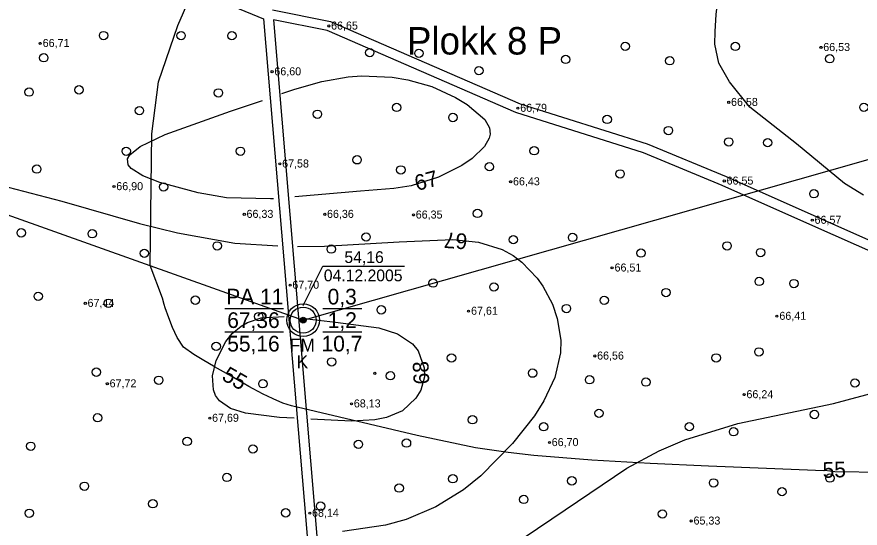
# Model space of a CAD drawing. Extents: x 532503 to 539665, y 6557663 to 6561526.
# Drawn here: x 534382.9 to 534640.9, y 6559631.8 to 6559788.4 of the extents above; entities that cross this region are included whole.
import ezdxf

# ---------------------------------------------------------------- set-up
doc = ezdxf.new("R2010")
doc.units = 0
for name, color, linetype in [('GEOLPUNKT', 7, 'Continuous'), ('HALJASTUS', 7, 'Continuous'), ('HORISONTAAL-EH2000', 7, 'Continuous'), ('KORGUS-EH2000', 7, 'Continuous'), ('Lamami horisontaal_EH2000', 7, 'Continuous'), ('Lõige', 7, 'Continuous'), ('Plokid', 7, 'Continuous'), ('Proovid', 7, 'Continuous'), ('TEE', 7, 'Continuous'), ('Veetase', 7, 'Continuous')]:
    doc.layers.add(name, color=color, linetype=linetype)

# ---------------------------------------------------------------- blocks, each defined once
blk = doc.blocks.new('METS')
at = {"layer": 'HALJASTUS'}
blk.add_circle((0, 0), 0.8, dxfattribs=at)

msp = doc.modelspace()

# ---------------------------------------------------------------- linework, layer by layer
at = {"layer": 'GEOLPUNKT'}
for p, q in [((534446.46, 6559699.1), (534464.46, 6559699.1)), ((534476.46, 6559699.1), (534488.46, 6559699.1)), ((534446.46, 6559691.9), (534464.46, 6559691.9)), ((534476.46, 6559691.9), (534488.46, 6559691.9))]:
    msp.add_line(p, q, dxfattribs=at)
for radius in [5, 4, 0.9, 0.801, 0.7, 0.6, 0.5, 0.4, 0.3, 0.2, 0.1]:
    msp.add_circle((534470.46, 6559695.5), radius, dxfattribs=at)
at = {"layer": 'HORISONTAAL-EH2000'}
for points in [[(534463.98, 6559764.86), (534467.88, 6559766.2), (534476.15, 6559768.55), (534484.2, 6559769.98), (534488.32, 6559770.29), (534497.69, 6559769.93), (534502.54, 6559769.12), (534509.88, 6559767.01), (534517.13, 6559763.69), (534520.66, 6559761.54), (534526.09, 6559756.93), (534527.51, 6559754.38), (534527.66, 6559752.47), (534527.37, 6559751.19), (534525.95, 6559748.65), (534522.22, 6559745.02), (534519, 6559742.82), (534511.9, 6559739.24), (534503.48, 6559736.65), (534498.24, 6559735.82), (534487.98, 6559735.02), (534467.95, 6559733.26)], [(534416.88, 6559743.1), (534416.74, 6559744.91), (534417.46, 6559746.14), (534420.54, 6559748.62), (534428.26, 6559752.34), (534448.28, 6559759.44), (534458, 6559762.8)], [(534461.38, 6559732.68), (534460.49, 6559732.6), (534447, 6559732.94), (534438.35, 6559734.48), (534426.58, 6559737.68), (534421.41, 6559739.72), (534417.82, 6559741.94), (534416.88, 6559743.1)], [(534304.83, 6559710.87), (534306.86, 6559714.66), (534312.1, 6559721.64), (534318.6, 6559727.68), (534323.47, 6559731.11), (534330.43, 6559734.83), (534334.03, 6559736.29), (534340.72, 6559738.23), (534345.25, 6559739.05), (534354.44, 6559739.68), (534368.46, 6559738.57), (534377.87, 6559736.8), (534396.57, 6559731.9), (534420.34, 6559725.11), (534432.05, 6559722.19), (534449.59, 6559719.1), (534462.68, 6559718.26)], [(534468.76, 6559718.08), (534476.98, 6559718.15), (534499.85, 6559719.5), (534516.26, 6559720.19), (534524.11, 6559719.37), (534531.39, 6559717.1), (534534.73, 6559715.26), (534537.38, 6559713.3), (534542.07, 6559708.39), (534543.84, 6559705.87), (534546.73, 6559700.39), (534548.23, 6559696.03), (534549.28, 6559689.36), (534549.16, 6559685.49), (534547.43, 6559677.98), (534544.1, 6559670.82), (534541.23, 6559666.25), (534534.5, 6559657.68), (534524.79, 6559647.82), (534519.55, 6559643.58), (534511.05, 6559638.29), (534501.98, 6559634.51), (534495.61, 6559632.72), (534482.49, 6559630.74)], [(534448.77, 6559691.44), (534451.45, 6559693.69), (534453.39, 6559694.79), (534457.61, 6559696.17), (534464.65, 6559696.66), (534464.69, 6559696.66)], [(534469.96, 6559696.06), (534480.31, 6559694.89), (534493.61, 6559693.12), (534499.34, 6559691.35), (534503.92, 6559688.26), (534505.65, 6559686.06), (534507.51, 6559680.93), (534507.61, 6559678.15), (534506.47, 6559674.09), (534504.99, 6559671.64), (534500.82, 6559667.76), (534495.95, 6559665.65), (534492.44, 6559664.96), (534485.3, 6559664.59), (534472.81, 6559665.21)], [(534467.75, 6559665.46), (534463.21, 6559665.69), (534452.84, 6559667), (534448.28, 6559668.45), (534444.83, 6559670.8), (534443.68, 6559672.4), (534442.99, 6559674.21), (534442.77, 6559678.48), (534443.83, 6559683.14), (534446.8, 6559689.01), (534448.77, 6559691.44)], [(534477.14, 6559615.14), (534484.93, 6559615.02), (534497.02, 6559615.08), (534503.03, 6559615.59), (534509.26, 6559616.62), (534521.34, 6559620.21), (534531.56, 6559625.05), (534538.08, 6559628.91), (534550.68, 6559637.44), (534569.5, 6559650.15), (534579.4, 6559655.53), (534587.21, 6559658.85), (534603.5, 6559663.82), (534632.76, 6559670.02), (534646.85, 6559673.77), (534665.59, 6559678.92), (534675.04, 6559680.97), (534698.41, 6559684.27), (534708.64, 6559686.35)]]:
    msp.add_lwpolyline(points, dxfattribs=at)
at = {"layer": 'KORGUS-EH2000'}
for centre in [(534478.31, 6559785.57), (534390, 6559780.24), (534628.91, 6559779.01), (534460.95, 6559771.57), (534536.18, 6559760.39), (534600.69, 6559762.19), (534463.34, 6559743.34), (534533.97, 6559737.88), (534599.34, 6559738.11), (534412.59, 6559736.41), (534452.45, 6559727.91), (534477.07, 6559727.91), (534504.21, 6559727.71), (534626.26, 6559726.1), (534564.99, 6559711.49), (534466.47, 6559706.22), (534403.8, 6559700.65), (534521.08, 6559698.25), (534615.42, 6559696.7), (534559.72, 6559684.53), (534492.42, 6559679.21), (534410.54, 6559676.03), (534605.42, 6559672.7), (534485.27, 6559669.88), (534441.9, 6559665.48), (534545.83, 6559658.03), (534472.48, 6559636.39), (534589.22, 6559634.01)]:
    msp.add_circle(centre, 0.32, dxfattribs=at)
at = {"layer": 'Lamami horisontaal_EH2000'}
for points in [[(534641.96, 6559733.8), (534636.15, 6559737.35), (534621.41, 6559749.49), (534607.16, 6559760.68), (534600.88, 6559768.5), (534597.64, 6559774.18), (534596.39, 6559780.02), (534596.55, 6559783.91), (534596.82, 6559789.06), (534597.63, 6559796.25), (534601.08, 6559812.52), (534601.39, 6559813.21), (534608.53, 6559834.71), (534618.81, 6559854.93), (534624.39, 6559863.19), (534625.8, 6559864.95), (534629.67, 6559870.31), (534637.21, 6559879.48), (534638.05, 6559880.42), (534643.05, 6559885.87)], [(534647.91, 6559648.87), (534633.11, 6559649.09), (534630.09, 6559649.44), (534629.74, 6559649.35), (534612.28, 6559650.1), (534594.46, 6559650.81), (534576.65, 6559651.63), (534558.84, 6559652.66), (534541.02, 6559654.08), (534533.22, 6559654.99), (534523.21, 6559656.43), (534505.39, 6559660.2), (534466.87, 6559669.23), (534464.28, 6559670.07), (534461.25, 6559671.38), (534459.53, 6559672.23), (534458.21, 6559672.88), (534455.18, 6559674.51), (534453.89, 6559675.23), (534452.15, 6559676.22), (534449.12, 6559677.94), (534448.6, 6559678.23), (534446.08, 6559679.7), (534443.32, 6559681.23), (534443.05, 6559681.39), (534440.02, 6559683.15), (534436.99, 6559684.93), (534433.89, 6559687.23), (534431.91, 6559690.22), (534430.46, 6559693.22), (534429.32, 6559696.22), (534428.25, 6559699.22), (534427.89, 6559700.32), (534427.38, 6559702.22), (534423.61, 6559712.2), (534424.2, 6559752.56), (534426.15, 6559768.44), (534432.16, 6559785.73), (534439.73, 6559803.35)]]:
    msp.add_lwpolyline(points, dxfattribs=at)
at = {"layer": 'Lõige'}
msp.add_lwpolyline([(533917.43, 6559650.43), (533949.04, 6559659.85), (534215.74, 6559786.31), (534470.46, 6559695.5), (534707.91, 6559763.06), (534929.16, 6559826.01), (535198.18, 6559814.49), (535305.66, 6559887.85), (535520.8, 6559960.87), (535543.92, 6559971)], dxfattribs=at)
at = {"layer": 'TEE'}
msp.add_line((534477.79, 6559784.16), (534461.34, 6559787.47), dxfattribs=at)
for points in [[(534402.87, 6559810.57), (534440.01, 6559795.43), (534458.31, 6559787.71)], [(534461.08, 6559790.53), (534478.84, 6559786.97), (534536.82, 6559761.75), (534575.75, 6559749.46), (534599.95, 6559739.48), (534655.41, 6559714.82), (534683.38, 6559701.33), (534712.77, 6559688.53)], [(534458.31, 6559787.71), (534465.26, 6559705.49), (534471.36, 6559633.06), (534479.39, 6559537.17), (534485.16, 6559471.19)], [(534461.34, 6559787.47), (534475.27, 6559622.04), (534487.82, 6559471.41)], [(534713.08, 6559685.13), (534682.1, 6559698.62), (534654.11, 6559712.12), (534625.54, 6559724.78), (534598.72, 6559736.74), (534574.63, 6559746.68), (534535.55, 6559759.03), (534477.79, 6559784.16)]]:
    msp.add_lwpolyline(points, dxfattribs=at)
at = {"layer": 'Veetase'}
for p, q in [((534470.46, 6559700), (534476.46, 6559712)), ((534476.46, 6559712), (534501.46, 6559712))]:
    msp.add_line(p, q, dxfattribs=at)

# ---------------------------------------------------------------- block references
at = {"layer": 'HALJASTUS', "xscale": 1.6, "yscale": 1.6000000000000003}
for p in [(534409.4, 6559782.62), (534433.11, 6559782.61), (534448.67, 6559782.59), (534490.83, 6559777.41), (534505.87, 6559777.2), (534569.01, 6559779.33), (534602.71, 6559779.31), (534391.08, 6559775.83), (534550.78, 6559775.33), (534582.64, 6559774.93), (534631.6, 6559775.53), (534524.24, 6559771.88), (534386.59, 6559765.34), (534401.88, 6559766.02), (534444.54, 6559765.08), (534420.37, 6559759.65), (534499.07, 6559760.64), (534642.05, 6559760.67), (534474.82, 6559758.55), (534516.27, 6559757.55), (534563.49, 6559756.96), (534582.23, 6559753.53), (534600.71, 6559750.07), (534612.61, 6559749.83), (534416.33, 6559747.2), (534451.26, 6559747.23), (534541.15, 6559747.37), (534486.98, 6559744.59), (534388.96, 6559741.75), (534500.35, 6559741.5), (534527.47, 6559742.48), (534567.43, 6559740.29), (534427.76, 6559736.28), (534626.74, 6559734.19), (534523.81, 6559728.16), (534384.21, 6559722.23), (534405.91, 6559721.94), (534489.72, 6559720.95), (534552.9, 6559720.83), (534444.18, 6559718.24), (534534.77, 6559720.13), (534600.19, 6559718.22), (534421.87, 6559715.96), (534479.04, 6559717.26), (534573.84, 6559716.03), (534610.43, 6559716.2), (534610.01, 6559707.36), (534510.23, 6559706.85), (534528.84, 6559705.66), (534620.62, 6559706.71), (534389.41, 6559702.8), (534581.49, 6559703.94), (534410.89, 6559700.68), (534437.46, 6559701.62), (534562.61, 6559701.56), (534494.34, 6559698.66), (534551.01, 6559699.03), (534456.88, 6559696.59), (534443.84, 6559687.48), (534609.93, 6559685.79), (534479.19, 6559682.7), (534515.86, 6559683.92), (534596.84, 6559683.94), (534407.18, 6559679.57), (534540.68, 6559679.27), (534426.28, 6559677.11), (534497.15, 6559678.46), (534558.11, 6559677.26), (534575.33, 6559676.54), (534458.16, 6559676.03), (534639.3, 6559676.25), (534560.98, 6559666.98), (534626.91, 6559666.61), (534407.57, 6559665.61), (534522.28, 6559664.99), (534544.06, 6559662.85), (534588.63, 6559662.88), (534602.17, 6559661.32), (534434.97, 6559658.35), (534387.11, 6559656.88), (534455.08, 6559656.05), (534487.36, 6559657.47), (534502.08, 6559657.84), (534447.14, 6559647.33), (534516.26, 6559646.94), (534552.68, 6559646.3), (534596.04, 6559645.67), (534631.64, 6559647.13), (534403.54, 6559644.65), (534499.84, 6559644.07), (534616.99, 6559642.97), (534537.98, 6559640.62), (534424.46, 6559639.29), (534475.79, 6559638.54), (534386.66, 6559636.37), (534465.1, 6559636.5), (534580.4, 6559636.15)]:
    msp.add_blockref('METS', p, dxfattribs=at)

# ---------------------------------------------------------------- texts
at = {"layer": 'GEOLPUNKT'}
for s, p in [('PA 11', (534446.94, 6559700.3)), ('0,3', (534477.95, 6559700.3)), ('67,36', (534447.22, 6559693.1)), ('1,2', (534477.98, 6559693.1)), ('55,16', (534447.22, 6559685.9)), ('10,7', (534476.09, 6559685.9))]:
    msp.add_text(s, height=4.8, dxfattribs=at).set_placement(p)
at = {"layer": 'HORISONTAAL-EH2000'}
for s, rotation, p in [('67', 14.9042, (534505.29, 6559735.02)), ('67', 176.1561, (534520.85, 6559721.94)), ('68', 92.8187, (534509.1, 6559675.93))]:
    msp.add_text(s, height=4.8, rotation=rotation, dxfattribs=at).set_placement(p)
at = {"layer": 'KORGUS-EH2000'}
for s, p in [('66,65', (534479.01, 6559784.47)), ('66,71', (534390.76, 6559779.14)), ('66,53', (534629.61, 6559777.91)), ('66,60', (534461.65, 6559770.47)), ('66,58', (534601.39, 6559761.09)), ('66,79', (534536.88, 6559759.29)), ('67,58', (534464.03, 6559742.24)), ('66,90', (534413.28, 6559735.3)), ('66,43', (534534.67, 6559736.78)), ('66,55', (534600.03, 6559737.01)), ('66,33', (534453.14, 6559726.81)), ('66,36', (534477.76, 6559726.81)), ('66,35', (534504.91, 6559726.61)), ('66,57', (534626.95, 6559725)), ('66,51', (534565.75, 6559710.39)), ('67,70', (534467.16, 6559705.12)), ('67,44', (534404.49, 6559699.55)), ('67,61', (534521.84, 6559697.15)), ('66,41', (534616.18, 6559695.6)), ('66,56', (534560.41, 6559683.43)), ('67,72', (534411.23, 6559674.93)), ('66,24', (534606.11, 6559671.6)), ('68,13', (534485.97, 6559668.78)), ('67,69', (534442.59, 6559664.38)), ('66,70', (534546.52, 6559656.93)), ('68,14', (534473.18, 6559635.29)), ('65,33', (534589.92, 6559632.91))]:
    msp.add_text(s, height=2.45, dxfattribs=at).set_placement(p)
at = {"layer": 'Lamami horisontaal_EH2000'}
for rotation, p in [(330.2521, (534445.27, 6559677.39)), (2.0241, (534629.48, 6559647.18))]:
    msp.add_text('55', height=4.8, rotation=rotation, dxfattribs=at).set_placement(p)
at = {"layer": 'Plokid'}
msp.add_text('Plokk 8 P', height=8.4, dxfattribs=at).set_placement((534502.23, 6559776.83))
at = {"layer": 'Proovid'}
for s, p in [('FM', (534466.34, 6559685.86)), ('K', (534468.44, 6559680.75))]:
    msp.add_text(s, height=4, dxfattribs=at).set_placement(p)
at = {"layer": 'Veetase'}
for s, p in [('54,16', (534483.08, 6559713)), ('04.12.2005', (534476.78, 6559707.4))]:
    msp.add_text(s, height=3.6, dxfattribs=at).set_placement(p)

doc.saveas('drawing.dxf')
